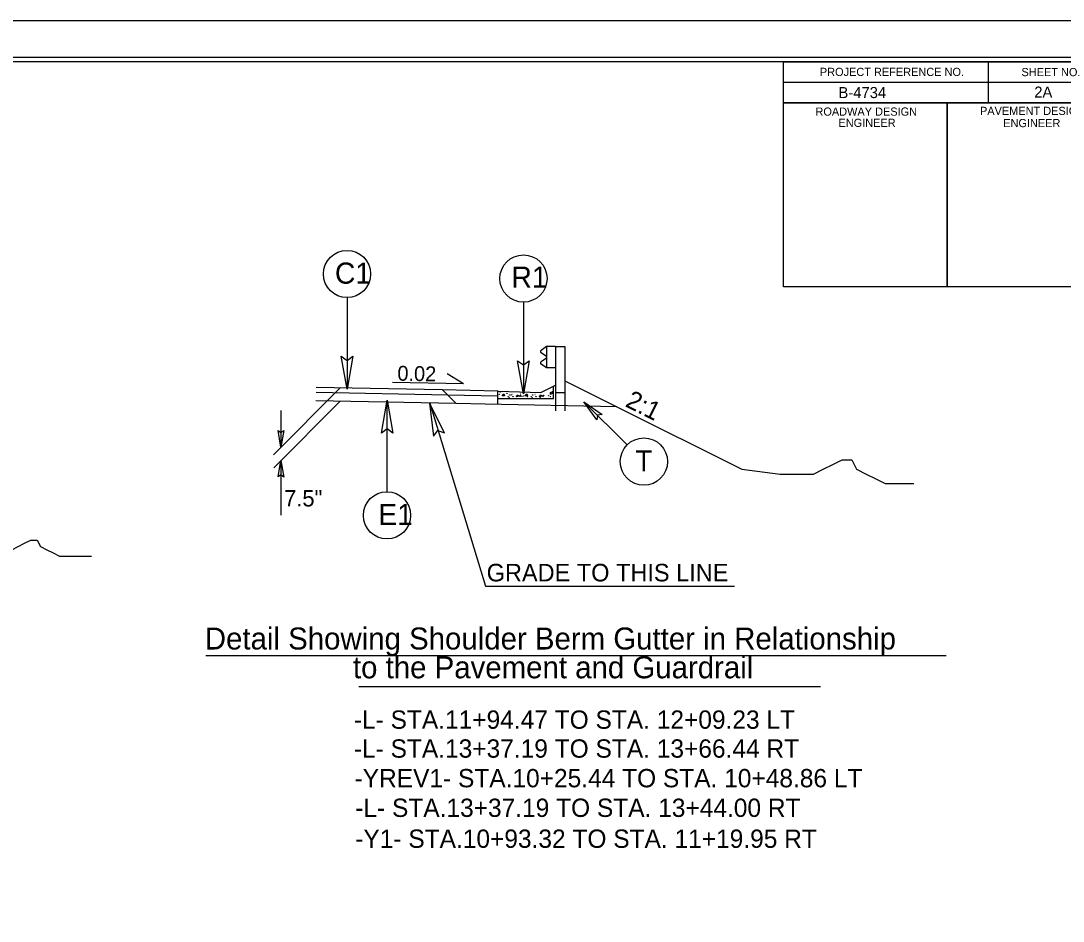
# Model space of a CAD drawing. Extents: x 1818040 to 1825768, y 638918 to 648046.
# Drawn here: x 1821432 to 1822069, y 644580 to 645130 of the extents above; entities that cross this region are included whole.
import ezdxf

# ---------------------------------------------------------------- set-up
doc = ezdxf.new("R2010")
doc.units = 0
for name, color, linetype in [('Old_Level_1', 7, 'Continuous'), ('Prop Dimension Text', 7, 'Continuous'), ('Sheet Data Field CELL', 7, 'Continuous'), ('Sheet Plot Border Inside CELL', 7, 'Continuous'), ('Sheet Plot Border Outside CELL', 7, 'Continuous'), ('Sheet Typical CELL', 7, 'Continuous'), ('Typical Curb CELL', 7, 'Continuous'), ('Typical Guardrail CELL', 7, 'Continuous'), ('Typical ID Circle CELL', 7, 'Continuous'), ('Typical Pavement Slope CELL', 7, 'Continuous'), ('Typical Pavement Slope Information CELL', 7, 'Continuous'), ('Typical Slope Point Local CELL', 7, 'Continuous'), ('Typical Terminator CELL', 7, 'Continuous'), ('Typical Text General CELL', 7, 'Continuous'), ('Typical Text Grade Point CELL', 7, 'Continuous'), ('Typical Text ID Circle CELL', 7, 'Continuous'), ('Typical Text Label CELL', 7, 'Continuous')]:
    doc.layers.add(name, color=color, linetype=linetype)

msp = doc.modelspace()

# ---------------------------------------------------------------- linework, layer by layer
at = {"layer": 'Old_Level_1'}
for p, q in [((1821757.38, 644906.37), (1821758.63, 644907)), ((1821627.05, 644905.37), (1821586.24, 644864.56)), ((1821692.84, 644900.93), (1821612.3, 644902.54)), ((1821689.65, 644904.12), (1821697.94, 644895.83)), ((1821723.4, 644900.32), (1821692.84, 644900.93)), ((1821627.05, 644897.24), (1821586.46, 644856.64)), ((1821697.94, 644895.83), (1821612.2, 644897.54)), ((1821681.73, 644896.15), (1821715.92, 644784.33)), ((1821715.67, 644895.47), (1821697.94, 644895.83)), ((1821796.09, 644893.86), (1821715.67, 644895.47)), ((1821723.4, 644895.32), (1821723.4, 644898.76)), ((1821590.83, 644891.52), (1821590.83, 644869.27)), ((1821590.83, 644861.02), (1821590.83, 644827.55)), ((1821715.92, 644784.33), (1821868.02, 644784.33))]:
    msp.add_line(p, q, dxfattribs=at)
at = {"layer": 'Sheet Plot Border Inside CELL'}
msp.add_lwpolyline([(1822110.43, 645107.18), (1820443.93, 645107.18), (1820443.93, 644052.08), (1822110.43, 644052.08)], close=True, dxfattribs=at)
at = {"layer": 'Sheet Plot Border Outside CELL'}
msp.add_lwpolyline([(1822114.93, 645129.63), (1820430.93, 645129.63), (1820430.93, 644029.63), (1822114.93, 644029.63)], close=True, dxfattribs=at)
at = {"layer": 'Sheet Typical CELL'}
for p, q in [((1822114.93, 645129.63), (1820430.93, 645129.63)), ((1822022.93, 645104.58), (1822022.93, 645079.58)), ((1821897.88, 645092.08), (1822097.93, 645092.08)), ((1821997.93, 645079.58), (1821997.93, 644967.13))]:
    msp.add_line(p, q, dxfattribs=at)
for points in [[(1822097.93, 645104.63), (1820597.93, 645104.63), (1820597.93, 644054.63), (1822097.93, 644054.63)], [(1821897.88, 645104.63), (1822097.93, 645104.63), (1822097.93, 645079.58), (1821897.88, 645079.58)], [(1821897.88, 645079.58), (1821997.93, 645079.58), (1821997.93, 644967.08), (1821897.88, 644967.08)], [(1821997.93, 645079.58), (1822097.93, 645079.58), (1822097.93, 644967.08), (1821997.93, 644967.08)]]:
    msp.add_lwpolyline(points, close=True, dxfattribs=at)
at = {"layer": 'Typical Curb CELL'}
for p, q in [((1821723.4, 644903.44), (1821723.4, 644903.44)), ((1821723.4, 644898.76), (1821723.4, 644903.32)), ((1821723.52, 644903.44), (1821749.65, 644902.5)), ((1821726.07, 644900.46), (1821727.05, 644901.81)), ((1821727.43, 644900.53), (1821726.07, 644900.46)), ((1821727.05, 644901.81), (1821727.43, 644900.53)), ((1821734.69, 644899.89), (1821735.39, 644901.18)), ((1821735.39, 644901.18), (1821736.55, 644900.34)), ((1821740.13, 644900.46), (1821741.1, 644901.81)), ((1821741.48, 644900.53), (1821740.13, 644900.46)), ((1821741.1, 644901.81), (1821741.48, 644900.53)), ((1821748.73, 644899.89), (1821749.44, 644901.18)), ((1821749.44, 644901.18), (1821750.6, 644900.34)), ((1821749.65, 644902.5), (1821757.38, 644906.37)), ((1821755.24, 644902.62), (1821755.42, 644901.6)), ((1821756.97, 644902.12), (1821755.24, 644902.62)), ((1821755.42, 644901.6), (1821756.97, 644902.12)), ((1821757.38, 644898.76), (1821757.38, 644906.37)), ((1821757.38, 644898.76), (1821723.4, 644898.76)), ((1821736.55, 644900.34), (1821734.69, 644899.89)), ((1821750.6, 644900.34), (1821748.73, 644899.89))]:
    msp.add_line(p, q, dxfattribs=at)
for centre in [(1821724.41, 644901.44), (1821724.84, 644902.85), (1821728.97, 644902.01), (1821730.64, 644901.05), (1821731.49, 644901.02), (1821732.05, 644901.37), (1821734.77, 644900.51), (1821737.27, 644900.9), (1821737.38, 644901.56), (1821739.11, 644900.47), (1821740.16, 644900.57), (1821744.69, 644901.05), (1821746.11, 644901.37), (1821748.82, 644900.51), (1821751.32, 644900.9), (1821754.21, 644900.57), (1821756.65, 644903.08), (1821729.64, 644900.01), (1821730.27, 644899.62), (1821732.58, 644900.07), (1821737.08, 644900.33), (1821738.02, 644899.95), (1821741.51, 644900.01), (1821743.69, 644900.01), (1821744.32, 644899.62), (1821746.63, 644900.07), (1821749.14, 644899.36), (1821751.13, 644900.33), (1821755.56, 644900.01)]:
    msp.add_circle(centre, 0.0902, dxfattribs=at)
msp.add_arc((1821723.52, 644903.32), 0.117, 87.95199, 180, dxfattribs=at)
at = {"layer": 'Typical Guardrail CELL'}
for p, q in [((1821753.04, 644930.61), (1821749.78, 644928.33)), ((1821753.04, 644924.62), (1821749.78, 644926.9)), ((1821758.63, 644930.61), (1821753.04, 644930.61)), ((1821753.04, 644930.61), (1821753.04, 644917.57)), ((1821758.63, 644930.61), (1821758.63, 644902.65)), ((1821758.63, 644930.61), (1821764.23, 644930.61)), ((1821764.23, 644930.61), (1821764.23, 644902.65)), ((1821753.04, 644923.57), (1821749.78, 644921.28)), ((1821753.04, 644917.57), (1821749.78, 644919.85)), ((1821753.04, 644924.09), (1821753.04, 644924.62)), ((1821753.04, 644924.09), (1821753.04, 644923.57)), ((1821758.63, 644917.57), (1821753.04, 644917.57)), ((1821758.63, 644902.65), (1821764.23, 644902.65)), ((1821758.63, 644902.65), (1821758.63, 644891.31)), ((1821764.23, 644902.65), (1821764.23, 644891.31))]:
    msp.add_line(p, q, dxfattribs=at)
for centre, start, end in [((1821750.28, 644927.61), 125.00297, 235.0112), ((1821750.28, 644920.57), 125.0059, 235.0366)]:
    msp.add_arc(centre, 0.874, start, end, dxfattribs=at)
at = {"layer": 'Typical ID Circle CELL'}
for p, q in [((1821631.25, 644960.57), (1821631.25, 644904.65)), ((1821739.02, 644957.77), (1821739.02, 644901.85)), ((1821655.67, 644841.96), (1821655.67, 644897.88)), ((1821802.37, 644870.58), (1821775.99, 644896.94))]:
    msp.add_line(p, q, dxfattribs=at)
for centre in [(1821631.25, 644974.99), (1821739.02, 644972.2), (1821812.56, 644860.38), (1821655.67, 644827.53), (1821655.67, 644827.53)]:
    msp.add_circle(centre, 14.43, dxfattribs=at)
at = {"layer": 'Typical Pavement Slope CELL'}
for p, q in [((1821689.65, 644904.12), (1821612.36, 644905.66)), ((1821723.4, 644903.44), (1821689.65, 644904.12))]:
    msp.add_line(p, q, dxfattribs=at)
at = {"layer": 'Typical Pavement Slope Information CELL'}
for q in [(1821692.32, 644913.97), (1821658.97, 644908.71)]:
    msp.add_line((1821702.46, 644907.84), q, dxfattribs=at)
at = {"layer": 'Typical Slope Point Local CELL'}
for p, q in [((1821764.23, 644909.79), (1821796.09, 644893.86)), ((1821796.09, 644893.86), (1821872.46, 644855.68))]:
    msp.add_line(p, q, dxfattribs=at)
for points in [[(1821872.46, 644855.68), (1821895.8, 644852.77), (1821901.63, 644852.77), (1821910.4, 644852.77), (1821916.23, 644852.77), (1821922.07, 644855.68), (1821927.9, 644858.61), (1821933.74, 644861.54), (1821939.57, 644861.54), (1821942.5, 644855.68), (1821948.34, 644852.77), (1821954.17, 644849.84), (1821960.01, 644846.94), (1821965.84, 644846.94), (1821971.68, 644846.94), (1821977.51, 644846.94)], [(1821397.3, 644808.49), (1821412.86, 644806.56), (1821416.75, 644806.56), (1821422.59, 644806.56), (1821426.48, 644806.56), (1821430.37, 644808.49), (1821434.26, 644810.45), (1821438.15, 644812.4), (1821442.04, 644812.4), (1821443.99, 644808.49), (1821447.88, 644806.56), (1821451.77, 644804.6), (1821455.66, 644802.67), (1821459.55, 644802.67), (1821463.44, 644802.67), (1821467.33, 644802.67), (1821471.22, 644802.67), (1821475.11, 644802.67)]]:
    msp.add_lwpolyline(points, dxfattribs=at)
at = {"layer": 'Typical Terminator CELL'}
for points in [[(1821634.7, 644924.68), (1821631.25, 644904.65), (1821627.68, 644924.79), (1821631.25, 644922.23)], [(1821742.47, 644921.88), (1821739.02, 644901.85), (1821735.46, 644921.99), (1821739.02, 644919.43)], [(1821652.22, 644877.84), (1821655.67, 644897.88), (1821659.23, 644877.73), (1821655.67, 644880.29)], [(1821690.81, 644877.94), (1821681.71, 644896.12), (1821684.13, 644875.81), (1821686.8, 644879.29)], [(1821783.82, 644885.87), (1821775.99, 644896.94), (1821787.17, 644889.12), (1821784.29, 644888.65)], [(1821592.64, 644879.27), (1821590.83, 644869.27), (1821589.13, 644879.36), (1821590.9, 644878.06)], [(1821589.14, 644850.99), (1821590.83, 644861.02), (1821592.65, 644850.95), (1821590.87, 644852.23)]]:
    msp.add_lwpolyline(points, close=True, dxfattribs=at)
at = {"layer": 'Typical Text Label CELL'}
for p, q in [((1821544.95, 644741.87), (1821997.26, 644741.87)), ((1821638.42, 644722.98), (1821920.51, 644722.98))]:
    msp.add_line(p, q, dxfattribs=at)

# ---------------------------------------------------------------- texts
at = {"layer": 'Prop Dimension Text'}
msp.add_text('7.5"', height=10, dxfattribs=at).set_placement((1821592.82, 644832.96))
at = {"layer": 'Sheet Data Field CELL'}
for s, p in [('B-4734   ', (1821931.44, 645082.43)), ('2A ', (1822051.03, 645082.73))]:
    msp.add_text(s, height=6.75, dxfattribs=at).set_placement(p)
at = {"layer": 'Sheet Typical CELL'}
for s, height, p in [('PROJECT REFERENCE NO.', 5.0001, (1821920.08, 645095.93)), ('SHEET NO.', 5, (1822043.23, 645095.83)), ('ROADWAY DESIGN', 5.0001, (1821917.38, 645071.68)), ('PAVEMENT DESIGN', 5.0001, (1822017.88, 645072.13)), ('ENGINEER', 5, (1821931.43, 645064.83)), ('ENGINEER', 5, (1822032.08, 645064.68))]:
    msp.add_text(s, height=height, dxfattribs=at).set_placement(p)
at = {"layer": 'Typical Pavement Slope Information CELL'}
msp.add_text('0.02 ', height=9.107, rotation=358.85426, dxfattribs=at).set_placement((1821661.93, 644909.84))
at = {"layer": 'Typical Text General CELL'}
msp.add_text('2:1 ', height=11.19, rotation=333.43495, dxfattribs=at).set_placement((1821800.6, 644894.37))
for s, height, p in [('GRADE TO THIS LINE', 10.742, (1821716.54, 644787.17)), ('Detail Showing Shoulder Berm Gutter in Relationship', 13.4275, (1821544.38, 644745.58)), (' to the Pavement and Guardrail', 13.4275, (1821629.86, 644727.98))]:
    msp.add_text(s, height=height, dxfattribs=at).set_placement(p)
at = {"layer": 'Typical Text Grade Point CELL'}
for s, p in [('-L- STA.11+94.47 TO STA. 12+09.23 LT', (1821635.41, 644697.16)), ('-L- STA.13+37.19 TO STA. 13+66.44 RT', (1821635.41, 644679.49)), ('-YREV1- STA.10+25.44 TO STA. 10+48.86 LT', (1821635.84, 644661.4)), ('-L- STA.13+37.19 TO STA. 13+44.00 RT', (1821636.27, 644643.3)), ('-Y1- STA.10+93.32 TO STA. 11+19.95 RT', (1821636.27, 644624.41))]:
    msp.add_text(s, height=11.1896, dxfattribs=at).set_placement(p)
at = {"layer": 'Typical Text ID Circle CELL'}
for s, height, p in [('C1', 12.912, (1821623.86, 644969.05)), ('R1', 12.921, (1821731.68, 644966.6)), ('T', 12.91, (1821807.28, 644854.43)), ('E1', 12.912, (1821650.34, 644821.59))]:
    msp.add_text(s, height=height, dxfattribs=at).set_placement(p)

doc.saveas('drawing.dxf')
